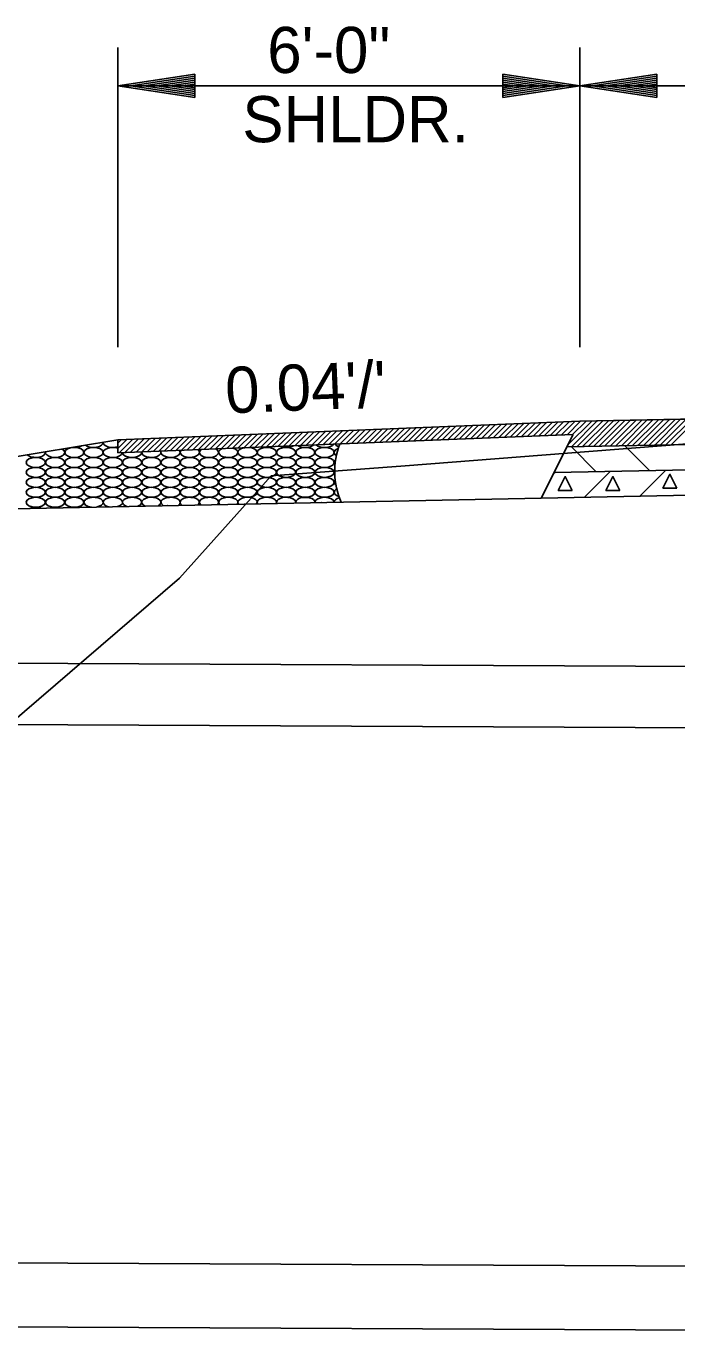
# Model space of a CAD drawing. Extents: x 1398460 to 1408037, y 380768 to 383968.
# Drawn here: x 1401307 to 1401391.5, y 383325.7 to 383495.8 of the extents above; entities that cross this region are included whole.
import ezdxf

# ---------------------------------------------------------------- set-up
doc = ezdxf.new("R2010")
doc.units = 0
for name, color, linetype in [('R_Dimension', 7, 'Continuous'), ('R_Draft', 7, 'Continuous'), ('R_Exist Surface', 7, 'Continuous'), ('R_Fin Surface', 7, 'Continuous'), ('R_Water', 7, 'Continuous')]:
    doc.layers.add(name, color=color, linetype=linetype)

msp = doc.modelspace()

# ---------------------------------------------------------------- linework, layer by layer
at = {"layer": 'R_Dimension'}
for p, q in [((1401318.88, 383492.99), (1401318.88, 383454)), ((1401378.88, 383492.99), (1401378.88, 383454)), ((1401328.88, 383489.49), (1401318.88, 383487.99)), ((1401328.88, 383489.24), (1401320.55, 383487.99)), ((1401328.88, 383488.98), (1401322.27, 383487.99)), ((1401328.88, 383488.73), (1401323.93, 383487.99)), ((1401328.88, 383488.48), (1401325.63, 383487.99)), ((1401328.88, 383486.49), (1401328.88, 383489.49)), ((1401368.88, 383489.49), (1401378.88, 383487.99)), ((1401368.88, 383486.49), (1401368.88, 383489.49)), ((1401368.88, 383489.24), (1401377.21, 383487.99)), ((1401368.88, 383488.98), (1401375.49, 383487.99)), ((1401368.88, 383488.73), (1401373.82, 383487.99)), ((1401368.88, 383488.48), (1401372.13, 383487.99)), ((1401388.88, 383489.49), (1401378.88, 383487.99)), ((1401388.88, 383489.24), (1401380.55, 383487.99)), ((1401388.88, 383488.98), (1401382.27, 383487.99)), ((1401388.88, 383488.73), (1401383.93, 383487.99)), ((1401388.88, 383488.48), (1401385.63, 383487.99)), ((1401388.88, 383486.49), (1401388.88, 383489.49)), ((1401318.88, 383487.99), (1401378.88, 383487.99)), ((1401328.88, 383486.49), (1401318.88, 383487.99)), ((1401328.88, 383486.74), (1401320.55, 383487.99)), ((1401328.88, 383486.99), (1401322.27, 383487.99)), ((1401328.88, 383487.24), (1401323.93, 383487.99)), ((1401328.88, 383487.5), (1401325.63, 383487.99)), ((1401328.88, 383488.22), (1401327.3, 383487.99)), ((1401328.88, 383487.75), (1401327.3, 383487.99)), ((1401368.88, 383488.22), (1401370.46, 383487.99)), ((1401368.88, 383486.49), (1401378.88, 383487.99)), ((1401368.88, 383487.5), (1401372.13, 383487.99)), ((1401368.88, 383486.99), (1401375.49, 383487.99)), ((1401368.88, 383486.74), (1401377.21, 383487.99)), ((1401368.88, 383487.24), (1401373.82, 383487.99)), ((1401368.88, 383487.75), (1401370.46, 383487.99)), ((1401388.88, 383486.49), (1401378.88, 383487.99)), ((1401378.88, 383487.99), (1401498.88, 383487.99)), ((1401388.88, 383486.74), (1401380.55, 383487.99)), ((1401388.88, 383486.99), (1401382.27, 383487.99)), ((1401388.88, 383487.24), (1401383.93, 383487.99)), ((1401388.88, 383487.5), (1401385.63, 383487.99)), ((1401388.88, 383488.22), (1401387.3, 383487.99)), ((1401388.88, 383487.75), (1401387.3, 383487.99))]:
    msp.add_line(p, q, dxfattribs=at)
at = {"layer": 'R_Draft'}
for p, q in [((1401498.88, 383446.78), (1401378.88, 383444.38)), ((1401378.88, 383444.38), (1401318.88, 383441.98)), ((1401369.86, 383442.32), (1401371.63, 383444.09)), ((1401370.6, 383442.35), (1401372.37, 383444.12)), ((1401371.33, 383442.38), (1401373.11, 383444.15)), ((1401372.07, 383442.41), (1401373.84, 383444.18)), ((1401372.81, 383442.43), (1401374.58, 383444.21)), ((1401373.54, 383442.46), (1401375.32, 383444.23)), ((1401374.28, 383442.49), (1401376.05, 383444.26)), ((1401375.02, 383442.52), (1401376.79, 383444.29)), ((1401375.75, 383442.55), (1401377.52, 383444.32)), ((1401376.49, 383442.58), (1401378.26, 383444.35)), ((1401377.23, 383442.61), (1401379, 383444.38)), ((1401377.35, 383441.32), (1401380.44, 383444.41)), ((1401377.79, 383441.05), (1401381.16, 383444.42)), ((1401377.96, 383442.64), (1401379.72, 383444.39)), ((1401378.51, 383441.07), (1401381.88, 383444.44)), ((1401379.24, 383441.08), (1401382.6, 383444.45)), ((1401379.96, 383441.1), (1401383.32, 383444.47)), ((1401380.68, 383441.11), (1401384.05, 383444.48)), ((1401381.4, 383441.13), (1401384.77, 383444.5)), ((1401382.12, 383441.14), (1401385.49, 383444.51)), ((1401382.84, 383441.16), (1401386.21, 383444.52)), ((1401383.56, 383441.17), (1401386.93, 383444.54)), ((1401384.29, 383441.18), (1401387.65, 383444.55)), ((1401385.01, 383441.2), (1401388.38, 383444.57)), ((1401385.73, 383441.21), (1401389.1, 383444.58)), ((1401386.45, 383441.23), (1401389.82, 383444.6)), ((1401387.17, 383441.24), (1401390.54, 383444.61)), ((1401387.89, 383441.26), (1401391.26, 383444.62)), ((1401388.62, 383441.27), (1401391.98, 383444.64)), ((1401389.34, 383441.29), (1401392.7, 383444.65)), ((1401390.06, 383441.3), (1401393.43, 383444.67)), ((1401390.78, 383441.31), (1401394.15, 383444.68)), ((1401378.01, 383442.64), (1401318.88, 383440.28)), ((1401327.14, 383440.61), (1401328.91, 383442.38)), ((1401327.88, 383440.64), (1401329.65, 383442.41)), ((1401328.61, 383440.67), (1401330.38, 383442.44)), ((1401329.35, 383440.7), (1401331.12, 383442.47)), ((1401330.09, 383440.73), (1401331.86, 383442.5)), ((1401330.82, 383440.76), (1401332.59, 383442.53)), ((1401331.56, 383440.78), (1401333.33, 383442.56)), ((1401332.3, 383440.81), (1401334.07, 383442.58)), ((1401333.03, 383440.84), (1401334.8, 383442.61)), ((1401333.77, 383440.87), (1401335.54, 383442.64)), ((1401334.51, 383440.9), (1401336.28, 383442.67)), ((1401335.24, 383440.93), (1401337.01, 383442.7)), ((1401335.98, 383440.96), (1401337.75, 383442.73)), ((1401336.72, 383440.99), (1401338.49, 383442.76)), ((1401337.45, 383441.02), (1401339.22, 383442.79)), ((1401338.19, 383441.05), (1401339.96, 383442.82)), ((1401338.93, 383441.08), (1401340.7, 383442.85)), ((1401339.66, 383441.11), (1401341.43, 383442.88)), ((1401340.4, 383441.14), (1401342.17, 383442.91)), ((1401341.14, 383441.17), (1401342.91, 383442.94)), ((1401341.87, 383441.2), (1401343.64, 383442.97)), ((1401342.61, 383441.23), (1401344.38, 383443)), ((1401343.35, 383441.26), (1401345.12, 383443.03)), ((1401344.08, 383441.29), (1401345.85, 383443.06)), ((1401344.82, 383441.31), (1401346.59, 383443.09)), ((1401345.55, 383441.34), (1401347.33, 383443.12)), ((1401346.29, 383441.37), (1401348.06, 383443.14)), ((1401347.03, 383441.4), (1401348.8, 383443.17)), ((1401347.76, 383441.43), (1401349.54, 383443.2)), ((1401348.5, 383441.46), (1401350.27, 383443.23)), ((1401349.24, 383441.49), (1401351.01, 383443.26)), ((1401349.97, 383441.52), (1401351.74, 383443.29)), ((1401350.71, 383441.55), (1401352.48, 383443.32)), ((1401351.45, 383441.58), (1401353.22, 383443.35)), ((1401352.18, 383441.61), (1401353.95, 383443.38)), ((1401352.92, 383441.64), (1401354.69, 383443.41)), ((1401353.66, 383441.67), (1401355.43, 383443.44)), ((1401354.39, 383441.7), (1401356.16, 383443.47)), ((1401355.13, 383441.73), (1401356.9, 383443.5)), ((1401355.87, 383441.76), (1401357.64, 383443.53)), ((1401356.6, 383441.79), (1401358.37, 383443.56)), ((1401357.34, 383441.82), (1401359.11, 383443.59)), ((1401358.08, 383441.85), (1401359.85, 383443.62)), ((1401358.81, 383441.87), (1401360.58, 383443.65)), ((1401359.55, 383441.9), (1401361.32, 383443.67)), ((1401360.29, 383441.93), (1401362.06, 383443.7)), ((1401361.02, 383441.96), (1401362.79, 383443.73)), ((1401361.76, 383441.99), (1401363.53, 383443.76)), ((1401362.5, 383442.02), (1401364.27, 383443.79)), ((1401363.23, 383442.05), (1401365, 383443.82)), ((1401363.97, 383442.08), (1401365.74, 383443.85)), ((1401364.71, 383442.11), (1401366.48, 383443.88)), ((1401365.44, 383442.14), (1401367.21, 383443.91)), ((1401366.18, 383442.17), (1401367.95, 383443.94)), ((1401366.92, 383442.2), (1401368.69, 383443.97)), ((1401367.65, 383442.23), (1401369.42, 383444)), ((1401368.39, 383442.26), (1401370.16, 383444.03)), ((1401369.12, 383442.29), (1401370.9, 383444.06)), ((1401498.88, 383443.48), (1401377.21, 383441.04)), ((1401378.01, 383442.64), (1401377.21, 383441.04)), ((1401259.56, 383432.09), (1401318.88, 383441.98)), ((1401318.88, 383440.83), (1401320.07, 383442.03)), ((1401318.88, 383441.54), (1401319.34, 383442)), ((1401318.88, 383441.98), (1401318.88, 383440.28)), ((1401319.04, 383440.28), (1401320.81, 383442.05)), ((1401319.77, 383440.31), (1401321.55, 383442.08)), ((1401320.51, 383440.34), (1401322.28, 383442.11)), ((1401321.25, 383440.37), (1401323.02, 383442.14)), ((1401321.98, 383440.4), (1401323.76, 383442.17)), ((1401322.72, 383440.43), (1401324.49, 383442.2)), ((1401323.46, 383440.46), (1401325.23, 383442.23)), ((1401324.19, 383440.49), (1401325.97, 383442.26)), ((1401324.93, 383440.52), (1401326.7, 383442.29)), ((1401325.67, 383440.55), (1401327.44, 383442.32)), ((1401326.4, 383440.58), (1401328.17, 383442.35)), ((1401375.55, 383437.71), (1401377.21, 383441.04)), ((1401377.79, 383441.05), (1401381.03, 383437.82)), ((1401384.73, 383441.19), (1401387.96, 383437.96)), ((1401498.88, 383440.18), (1401375.55, 383437.71)), ((1401375.55, 383437.71), (1401373.88, 383434.38)), ((1401375.45, 383437.53), (1401375.64, 383437.71)), ((1401379.49, 383434.49), (1401382.85, 383437.86)), ((1401386.7, 383434.63), (1401390.07, 383438)), ((1401498.88, 383436.88), (1401373.88, 383434.38)), ((1401259.56, 383432.09), (1401373.88, 383434.38))]:
    msp.add_line(p, q, dxfattribs=at)
msp.add_lwpolyline([(1401318.88, 383441.98), (1401378.88, 383444.38), (1401498.88, 383446.78)], dxfattribs=at)
for points in [[(1401391.49, 383435.68), (1401389.69, 383435.68), (1401390.59, 383437.48)], [(1401377.89, 383435.38), (1401376.09, 383435.38), (1401376.99, 383437.18)], [(1401384.09, 383435.38), (1401382.29, 383435.38), (1401383.19, 383437.18)]]:
    msp.add_lwpolyline(points, close=True, dxfattribs=at)
msp.add_arc((1401357.05, 383437.87), 10, 159.167, 203.6836, dxfattribs=at)
for centre, major_axis, start_param, end_param in [((1401310.72, 383440.32), (-1.25, 0), 6.138235, 10.192432), ((1401313.22, 383441.61), (-1.25, 0), 1.328319, 2.435978), ((1401315.72, 383441.61), (-1.25, 0), 0.551478, 3.21282), ((1401318.22, 383440.32), (-1.25, 0), 4.849419, 9.40002), ((1401318.22, 383441.61), (-1.25, 0), 6.210283, 8.411155), ((1401318.22, 383440.32), (-1.25, 0), 4.155216, 4.849419), ((1401328.22, 383440.32), (-1.25, 0), 5.81997, 10.042161), ((1401330.72, 383440.32), (-1.25, 0), 5.825431, 10.233927), ((1401330.72, 383440.32), (-1.25, 0), 5.628204, 5.825431), ((1401333.22, 383440.32), (-1.25, 0), 5.394615, 10.467516), ((1401335.72, 383440.32), (-1.25, 0), 5.983515, 10.855139), ((1401335.72, 383440.32), (-1.25, 0), 5.006993, 5.983515), ((1401338.23, 383441.61), (-1.25, 0), 1.119473, 2.176288), ((1401340.73, 383441.61), (-1.25, 0), 0.866009, 2.429751), ((1401343.23, 383441.61), (-1.25, 0), 0.666147, 2.629614), ((1401345.73, 383441.61), (-1.25, 0), 0.490312, 2.805449), ((1401348.23, 383440.32), (-1.25, 0), 5.334622, 6.159373), ((1401348.23, 383441.61), (-1.25, 0), 0.327238, 1.015994), ((1401308.21, 383440.32), (-1.25, 0), 0.484273, 3.280024), ((1401320.72, 383440.32), (-1.25, 0), 0.024711, 3.27105), ((1401323.22, 383440.32), (-1.25, 0), 6.152412, 9.709719), ((1401325.72, 383440.32), (-1.25, 0), 5.991596, 9.870535), ((1401348.23, 383440.32), (-1.25, 0), 6.159373, 6.965221), ((1401348.23, 383439.02), (-1.25, 0), 6.24222, 6.705251), ((1401348.23, 383439.02), (-1.25, 0), 5.737231, 6.24222), ((1401348.23, 383437.73), (-1.25, 0), 6.0988, 6.636436), ((1401348.23, 383437.73), (-1.25, 0), 5.944556, 6.0988), ((1401348.23, 383436.43), (-1.25, 0), 5.812832, 6.282957), ((1401348.23, 383436.43), (-1.25, 0), 6.282957, 6.910119), ((1401348.23, 383435.14), (-1.25, 0), 5.531099, 5.941322), ((1401315.72, 383433.84), (-1.25, 0), 4.537473, 7.640512), ((1401315.72, 383433.84), (-1.25, 0), 1.861835, 4.537473), ((1401318.22, 383433.84), (-1.25, 0), 4.155216, 7.422177), ((1401318.22, 383433.84), (-1.25, 0), 2.08035, 4.155216), ((1401320.72, 383433.84), (-1.25, 0), 5.244863, 7.273116), ((1401320.72, 383433.84), (-1.25, 0), 2.229247, 5.244863), ((1401323.22, 383433.84), (-1.25, 0), 2.415789, 7.150327), ((1401325.72, 383433.84), (-1.25, 0), 5.373589, 7.04224), ((1401325.72, 383433.84), (-1.25, 0), 2.459907, 5.373589), ((1401328.22, 383433.84), (-1.25, 0), 2.626854, 6.943594), ((1401330.72, 383433.84), (-1.25, 0), 5.336209, 6.851513), ((1401330.72, 383433.84), (-1.25, 0), 2.65055, 5.336209), ((1401333.22, 383433.84), (-1.25, 0), 2.812898, 6.764197), ((1401335.72, 383433.84), (-1.25, 0), 5.313728, 6.680366), ((1401335.72, 383433.84), (-1.25, 0), 2.821761, 5.313728), ((1401338.23, 383433.84), (-1.25, 0), 4.490969, 6.5991), ((1401338.23, 383433.84), (-1.25, 0), 2.903075, 4.490969), ((1401340.73, 383433.84), (-1.25, 0), 3.072542, 6.519677), ((1401343.23, 383433.84), (-1.25, 0), 3.15697, 6.441502), ((1401345.73, 383433.84), (-1.25, 0), 3.138261, 6.27109), ((1401348.23, 383435.14), (-1.25, 0), 5.941322, 7.336025), ((1401348.23, 383433.84), (-1.25, 0), 5.180551, 6.276181), ((1401308.21, 383432.55), (-1.25, 0), 4.105305, 5.396789), ((1401310.72, 383432.55), (-1.25, 0), 4.247409, 5.254719), ((1401310.32, 383431.81), (-2.5, -0.05), 4.708433, 4.716345), ((1401313.22, 383432.55), (-1.25, 0), 4.443289, 5.05904), ((1401315.32, 383431.91), (-2.5, -0.05), 4.708431, 4.716347), ((1401320.32, 383432.01), (-2.5, -0.05), 4.708428, 4.71635), ((1401323.22, 383433.84), (-1.25, 0), 2.351888, 2.415789), ((1401325.33, 383432.11), (-2.5, -0.05), 4.708425, 4.716353), ((1401328.22, 383433.84), (-1.25, 0), 2.5585, 2.626854), ((1401330.33, 383432.21), (-2.5, -0.05), 4.708422, 4.716356), ((1401333.22, 383433.84), (-1.25, 0), 2.737883, 2.812898), ((1401335.33, 383432.31), (-2.5, -0.05), 4.708419, 4.716359), ((1401340.73, 383433.84), (-1.25, 0), 2.982546, 3.072542), ((1401343.23, 383433.84), (-1.25, 0), 3.060768, 3.15697), ((1401345.73, 383433.84), (-1.25, 0), 6.27109, 6.364058), ((1401345.33, 383432.51), (-2.5, -0.05), 4.708414, 4.716364), ((1401348.23, 383433.84), (-1.25, 0), 6.276181, 6.286867)]:
    msp.add_ellipse(centre, major_axis=major_axis, ratio=0.517889, start_param=start_param, end_param=end_param, dxfattribs=at)
for centre in [(1401313.22, 383440.32), (1401315.72, 383440.32), (1401338.23, 383440.32), (1401340.73, 383440.32), (1401343.23, 383440.32), (1401345.73, 383440.32), (1401308.21, 383439.02), (1401310.72, 383439.02), (1401313.22, 383439.02), (1401315.72, 383439.02), (1401318.22, 383439.02), (1401320.72, 383439.02), (1401323.22, 383439.02), (1401325.72, 383439.02), (1401328.22, 383439.02), (1401330.72, 383439.02), (1401333.22, 383439.02), (1401335.72, 383439.02), (1401338.23, 383439.02), (1401340.73, 383439.02), (1401343.23, 383439.02), (1401345.73, 383439.02), (1401308.21, 383437.73), (1401310.72, 383437.73), (1401313.22, 383437.73), (1401315.72, 383437.73), (1401318.22, 383437.73), (1401320.72, 383437.73), (1401323.22, 383437.73), (1401325.72, 383437.73), (1401328.22, 383437.73), (1401330.72, 383437.73), (1401333.22, 383437.73), (1401335.72, 383437.73), (1401338.23, 383437.73), (1401340.73, 383437.73), (1401343.23, 383437.73), (1401345.73, 383437.73), (1401308.21, 383436.43), (1401308.21, 383435.14), (1401310.72, 383436.43), (1401310.72, 383435.14), (1401313.22, 383436.43), (1401313.22, 383435.14), (1401315.72, 383436.43), (1401315.72, 383435.14), (1401318.22, 383436.43), (1401318.22, 383435.14), (1401320.72, 383436.43), (1401320.72, 383435.14), (1401323.22, 383436.43), (1401323.22, 383435.14), (1401325.72, 383436.43), (1401325.72, 383435.14), (1401328.22, 383436.43), (1401328.22, 383435.14), (1401330.72, 383436.43), (1401330.72, 383435.14), (1401333.22, 383436.43), (1401333.22, 383435.14), (1401335.72, 383436.43), (1401335.72, 383435.14), (1401338.23, 383436.43), (1401338.23, 383435.14), (1401340.73, 383436.43), (1401340.73, 383435.14), (1401343.23, 383436.43), (1401343.23, 383435.14), (1401345.73, 383436.43), (1401345.73, 383435.14), (1401308.21, 383433.84), (1401310.72, 383433.84), (1401313.22, 383433.84)]:
    msp.add_ellipse(centre, major_axis=(-1.25, 0), ratio=0.517889, dxfattribs=at)
at = {"layer": 'R_Exist Surface'}
msp.add_lwpolyline([(1400860.62, 383376.7), (1400907, 383354.28), (1400940.86, 383332.12), (1401045.76, 383333.11), (1401151.13, 383326.36), (1401196.75, 383331.07), (1401202.25, 383331.58), (1401276.34, 383380.48), (1401326.87, 383423.96), (1401338.8, 383437.28), (1401356.21, 383438.58), (1401392.29, 383441.42), (1401426.8, 383442.84), (1401496.14, 383445.51), (1401531.37, 383445.32), (1401595.85, 383444.59), (1401631.24, 383442.98), (1401649.93, 383442.13), (1401667.5, 383439.36), (1401669.33, 383438.98), (1401672.56, 383434.42), (1401687.05, 383422.29), (1401773.43, 383346.69)], dxfattribs=at)
at = {"layer": 'R_Fin Surface'}
msp.add_line((1401318.88, 383441.98), (1401164.2, 383416.2), dxfattribs=at)
at = {"layer": 'R_Water'}
for p, q in [((1401498.88, 383411.98), (1401164.2, 383413.56)), ((1401154.2, 383405.64), (1401498.88, 383404.05)), ((1401498.88, 383334.05), (1401063.08, 383336.06)), ((1401063.08, 383327.72), (1401498.88, 383325.71))]:
    msp.add_line(p, q, dxfattribs=at)

# ---------------------------------------------------------------- texts
at = {"layer": 'R_Dimension'}
for s, p in [('6\'-0"', (1401338.29, 383489.66)), ('SHLDR.', (1401335.05, 383480.66))]:
    msp.add_text(s, height=6, dxfattribs=at).set_placement(p)
at = {"layer": 'R_Draft'}
msp.add_text("0.04'/'", height=6, rotation=2.2906, dxfattribs=at).set_placement((1401332.94, 383445.4))

doc.saveas('drawing.dxf')
